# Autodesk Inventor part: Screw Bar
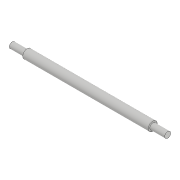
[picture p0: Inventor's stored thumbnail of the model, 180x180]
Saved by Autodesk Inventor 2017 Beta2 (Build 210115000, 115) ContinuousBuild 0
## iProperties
Created: 2016-03
Part Number: Screw Bar
Material: Generic
Document SubType Name: Modeling
Designer: Sandeep
Density: 1 g/cm^3
Appearance: Default
Author: Sandeep
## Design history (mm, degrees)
sketch "Sketch1"
  geometry: L1 (-104, 2)-(-94, 2); L2 (-94, 2)-(-94, 3); L3 (-94, 3)-(-10, 3); L4 (-10, 3)-(-10, 2); L5 (-10, 2)-(0, 2); L6 (0, 2)-(0, 0); L7 (-104, 2)-(-104, 0); L8 (-104, 0)-(0, 0); L9 (0, 0)-(21.698, 0)
  constraints: 18 end point, 4 perpendicular, 3 horizontal, 2 point on line, 1 vertical
  dimensions: "d0" = 4 diameter of L5 L9; "d1" = 6 diameter of L3 L9; "d2" = 10 distance of L4.end L5.end; "d3" = 10 distance of L1.start L1.end; "d4" = 104 distance between parallel lines of L7 L6
revolve "Revolution1" sketch "Sketch1" stored, may be unused: angle "d5" = 90 deg
body "Solid1"
